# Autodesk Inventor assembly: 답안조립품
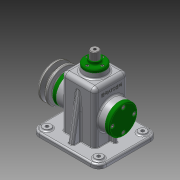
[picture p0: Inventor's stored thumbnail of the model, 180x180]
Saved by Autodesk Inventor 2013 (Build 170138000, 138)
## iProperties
Created: 2016-06
Part Number: 답안조립품
Document SubType Name: Assembly
Designer: home
Author: home
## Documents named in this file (19)
- C:\Users\home\Desktop\Manufacturing2급-홍성기\답안조립품.iam
- C:\Users\home\Desktop\Manufacturing2급-홍성기\본체.ipt
- C:\Users\home\Desktop\Manufacturing2급-홍성기\공용부품\앞커버.ipt
- C:\Users\home\Desktop\Manufacturing2급-홍성기\공용부품\뒤커버.ipt
- C:\Users\home\Desktop\Manufacturing2급-홍성기\공용부품\베어링 15 x 35 x 11.ipt
- C:\Users\home\Desktop\Manufacturing2급-홍성기\공용부품\편심축.ipt
- C:\Users\home\Desktop\Manufacturing2급-홍성기\공용부품\상부부시.ipt
- C:\Users\home\Desktop\Manufacturing2급-홍성기\공용부품\멈춤링 15 x 1.ipt
- C:\Users\home\Desktop\Manufacturing2급-홍성기\공용부품\오일실 15 25 7.ipt
- C:\Users\home\Desktop\Manufacturing2급-홍성기\공용부품\와셔.ipt
- C:\Users\home\Desktop\Manufacturing2급-홍성기\공용부품\볼트 M6 x 12.ipt
- C:\Users\home\Desktop\Manufacturing2급-홍성기\공용부품\키 5 x 5 x 14.ipt
- C:\Users\home\Desktop\Manufacturing2급-홍성기\공용부품\링크.ipt
- C:\Users\home\Desktop\Manufacturing2급-홍성기\공용부품\슬라이드바.ipt
- C:\Users\home\Desktop\Manufacturing2급-홍성기\공용부품\고정핀.ipt
- C:\Users\home\Desktop\Manufacturing2급-홍성기\공용부품\멈춤링 6 x 5.ipt
- C:\Users\home\Desktop\Manufacturing2급-홍성기\공용부품\볼트 M4 x 10.ipt
- C:\Users\home\Desktop\Manufacturing2급-홍성기\공용부품\볼트 M3 x 8.ipt
- C:\Users\home\Desktop\Manufacturing2급-홍성기\공용부품\V-벨트풀리.ipt
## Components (15 placed, 5 different names)
1. 고정핀:1
2. ISO 4018 M6 x 12:1
3. V-벨트풀리:1 — 각도:2
4. ISO 4762 M4 x 10:1
5. ISO 4762 M4 x 10:3
6. ISO 4762 M4 x 10:4
7. ISO 4762 M4 x 10:5
8. ISO 4762 M4 x 10:2
9. ISO 4762 M4 x 10:6
10. ISO 4762 M4 x 10:7
11. ISO 4762 M4 x 10:8
12. ISO 4762 M3 x 8:1
13. ISO 4762 M3 x 8:2
14. ISO 4762 M3 x 8:3
15. ISO 4762 M3 x 8:4
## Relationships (1: Angle 1)
- 각도:2 [Angle]: V-벨트풀리:1
